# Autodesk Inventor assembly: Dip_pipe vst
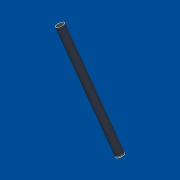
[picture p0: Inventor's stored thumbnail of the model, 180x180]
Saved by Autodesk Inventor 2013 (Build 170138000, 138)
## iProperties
Shininess: 20.0
Length Units: 11269
Angle Units: 11279
Time Units: 11290
Mass Units: 11283
Length Display Precision: 3
Angle Display Precision: 2
Created: 2001-04
Part Number: Dip_pipe vst
Document SubType Name: Baugruppe
Designer: dl
Density: 0.0
Volumn: 0.0
Area: 0.0
PropertySet Name: Model Information
Control State: 0
Master: False
Checked Out: False
Author: dl
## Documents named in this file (4)
- C:\Webworld\Webworld2014\ATC2013\Assemblies\ATC-Baby Carriage\DAMPER\Dip_pipe vst.iam
- C:\Webworld\Webworld2014\ATC2013\Assemblies\ATC-Baby Carriage\DAMPER\Dip_pipe.ipt
- C:\Webworld\Webworld2014\ATC2013\Assemblies\ATC-Baby Carriage\DAMPER\Inner_bush.ipt
- C:\Webworld\Webworld2014\ATC2013\Assemblies\ATC-Baby Carriage\DAMPER\Sliding_bush.ipt
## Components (3 placed, 3 different names)
1. Dip_pipe:1 — Insert:1
2. Inner_bush:1 — Insert:1, Insert:2
3. Sliding_bush:1 — Insert:2
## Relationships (2: Insert 2)
- Insert:1: Dip_pipe:1 ↔ Inner_bush:1
- Insert:2: Inner_bush:1 ↔ Sliding_bush:1
